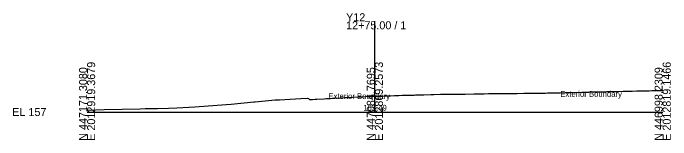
# Model space of a CAD drawing. Extents: x -26 to 1203, y -10 to 9542.
# Drawn here: x -25.7 to 202.8, y 5490.3 to 5534.4 of the extents above; entities that cross this region are included whole.
import ezdxf

# ---------------------------------------------------------------- set-up
doc = ezdxf.new("R2010")
doc.units = 0
for name, color, linetype in [('Default', 7, 'Continuous'), ('Exist Cross Section Cell', 7, 'Continuous'), ('Exist XS Center Line Elevation Label', 7, 'Continuous'), ('Exist XS Ground Line', 7, 'Continuous'), ('Scratch_Level_0', 7, 'Continuous')]:
    doc.layers.add(name, color=color, linetype=linetype)

msp = doc.modelspace()

# ---------------------------------------------------------------- linework, layer by layer
at = {"layer": 'Exist Cross Section Cell'}
for p, q in [((100, 5500), (100, 5531.58)), ((0, 5500), (100, 5500)), ((100, 5500), (200, 5500))]:
    msp.add_line(p, q, dxfattribs=at)
at = {"layer": 'Exist XS Ground Line'}
msp.add_lwpolyline([(0, 5500.68), (5.91, 5500.83), (18.42, 5501.07), (20.15, 5501.18), (24.47, 5501.26), (28.29, 5501.32), (31.21, 5501.49), (37.4, 5501.86), (48.32, 5502.56), (50.08, 5502.72), (57.88, 5503.5), (58.36, 5503.54), (65.33, 5504.2), (66.87, 5504.25), (74.22, 5504.71), (76.64, 5504.87), (76.95, 5504.65), (77.33, 5504.39), (78.37, 5504.41), (79.29, 5504.44), (79.88, 5504.47), (82.35, 5504.62), (83.15, 5504.67), (84.58, 5504.75), (85.23, 5504.79), (86.13, 5504.84), (88.11, 5504.96), (89.49, 5505.04), (90.98, 5505.11), (92.26, 5505.16), (94.09, 5505.24), (94.48, 5505.25), (95.92, 5505.32), (96.75, 5505.36), (99.64, 5505.48), (100, 5505.49), (101.41, 5505.53), (102.56, 5505.57), (103.27, 5505.6), (104.45, 5505.63), (105.45, 5505.67), (106.82, 5505.72), (108.34, 5505.78), (109.47, 5505.81), (110.6, 5505.85), (111.23, 5505.87), (113.64, 5505.92), (114.11, 5505.94), (114.46, 5505.94), (116.08, 5505.99), (117.01, 5506.01), (119.43, 5506.07), (119.87, 5506.09), (120.48, 5506.1), (122.75, 5506.16), (124.39, 5506.19), (125.64, 5506.2), (127.02, 5506.22), (128.53, 5506.24), (128.85, 5506.24), (129.38, 5506.24), (131.42, 5506.26), (134.37, 5506.29), (137.19, 5506.35), (137.98, 5506.38), (139.46, 5506.41), (140.08, 5506.42), (140.89, 5506.43), (142.96, 5506.45), (144.42, 5506.47), (145.31, 5506.47), (145.84, 5506.48), (147.83, 5506.49), (148.97, 5506.49), (149.44, 5506.5), (151.79, 5506.52), (154.56, 5506.55), (154.88, 5506.56), (157.46, 5506.59), (158.13, 5506.6), (159.26, 5506.61), (159.95, 5506.63), (160.35, 5506.63), (161.8, 5506.65), (163.23, 5506.68), (163.64, 5506.68), (164.38, 5506.7), (166.12, 5506.74), (168.62, 5506.81), (169.29, 5506.83), (171.9, 5506.9), (174.31, 5506.96), (174.79, 5506.97), (176.45, 5507.01), (177.68, 5507.04), (178.27, 5507.05), (179.28, 5507.07), (180.56, 5507.1), (181.92, 5507.12), (183.45, 5507.16), (183.75, 5507.17), (184.26, 5507.18), (186.32, 5507.22), (189.35, 5507.29), (191.07, 5507.32), (192.1, 5507.35), (192.44, 5507.35), (194.16, 5507.39), (194.73, 5507.41), (195.26, 5507.42), (196.26, 5507.45), (197.88, 5507.48), (199.29, 5507.52), (199.69, 5507.53), (200, 5507.53)], dxfattribs=at)

# ---------------------------------------------------------------- texts
at = {"layer": 'Default'}
msp.add_text('-', height=0.0001, dxfattribs=at).set_placement((0, 5500))
at = {"layer": 'Exist Cross Section Cell'}
for s, p in [('Y12', (90, 5531.58)), ('12+75.00 / 1', (90, 5528.78)), ('EL 157', (-26, 5498.6))]:
    msp.add_text(s, height=2.8, dxfattribs=at).set_placement(p)
for s, p in [('E 2012919.3679', (2.8, 5490)), ('E 2012869.2573', (102.8, 5490)), ('E 2012819.1466', (202.8, 5490)), ('N 447171.3080', (0, 5490)), ('N 447084.7695', (100, 5490)), ('N 446998.2309', (200, 5490))]:
    msp.add_text(s, height=2.8, rotation=90, dxfattribs=at).set_placement(p)
at = {"layer": 'Exist XS Center Line Elevation Label'}
msp.add_text('162.49', height=2, dxfattribs=at).set_placement((95.97, 5500.49))
at = {"layer": 'Scratch_Level_0'}
for p in [(83.85, 5504.53), (164.44, 5505.28)]:
    msp.add_text('Exterior Boundary', height=2, dxfattribs=at).set_placement(p)

doc.saveas('drawing.dxf')
